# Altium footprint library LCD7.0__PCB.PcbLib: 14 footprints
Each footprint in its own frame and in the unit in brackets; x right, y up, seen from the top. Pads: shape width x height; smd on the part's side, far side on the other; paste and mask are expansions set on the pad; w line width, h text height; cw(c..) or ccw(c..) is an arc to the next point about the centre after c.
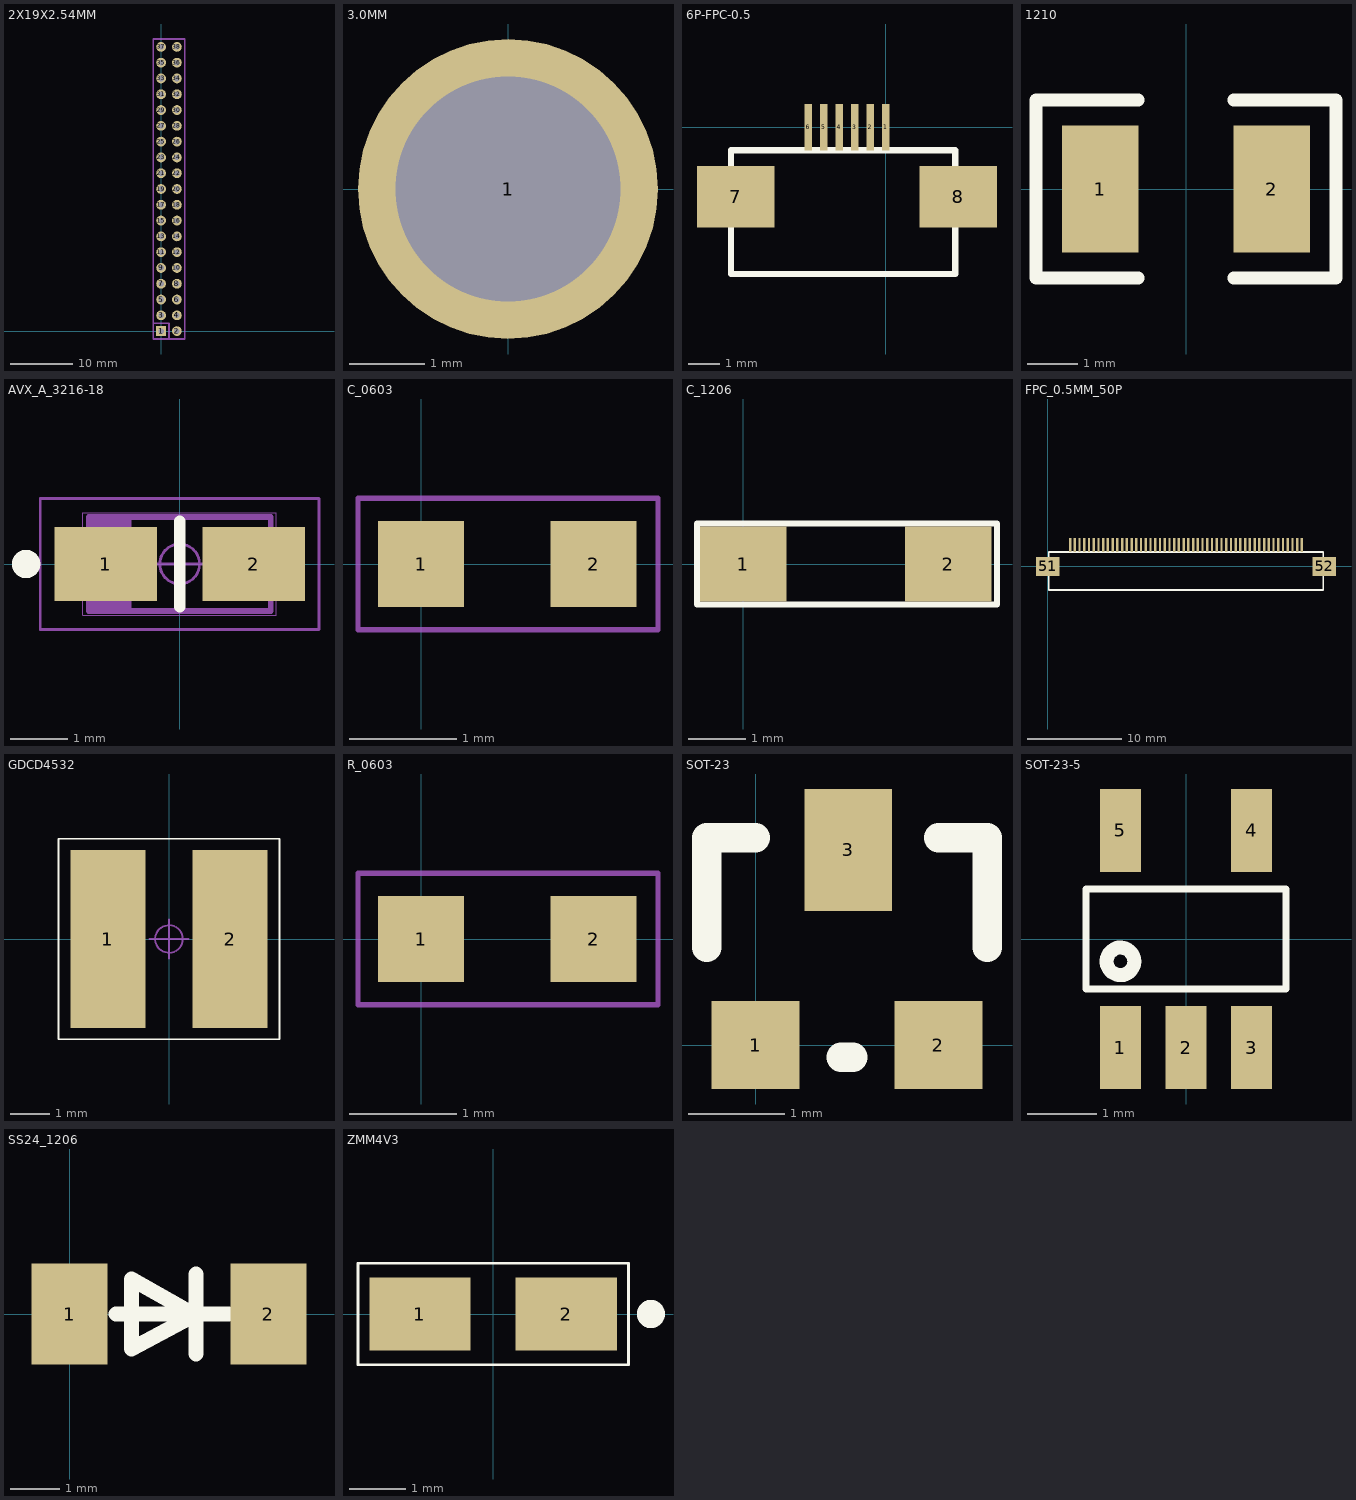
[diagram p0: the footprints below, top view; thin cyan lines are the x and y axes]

## 2X19X2.54MM [mil]
pads (38):
  rrect0% 62x62 hole 35.43: 1(0,0)
  round 62 hole 35.43: 2(100,0) 3(0,100) 4(100,100) 5(0,200) 6(100,200) 7(0,300) 8(100,300) 9(0,400) 10(100,400) 11(0,500) 12(100,500) 13(0,600) 14(100,600) 15(0,700) 16(100,700) 17(0,800) 18(100,800) 19(0,900) 20(100,900) 21(0,1000) 22(100,1000) 23(0,1100) 24(100,1100) 25(0,1200) 26(100,1200) 27(0,1300) 28(100,1300) 29(0,1400) 30(100,1400) 31(0,1500) 32(100,1500) 33(0,1600) 34(100,1600) 35(0,1700) 36(100,1700) 37(0,1800) 38(100,1800)
Mechanical 1:
  lines w12: -50,50 50,50 50,-50 ; -50,-50 150,-50 150,1850 -50,1850 -50,-50

## 3.0MM [mm]
pads (1):
  round 4 hole 3: 1(0,0)

## 6P-FPC-0.5 [mm]
height 5.3
pads (8):
  rect 0.25x1.5 smd: 1(0,0) 2(-0.5,0) 3(-1,0) 4(-1.5,0) 5(-2,0) 6(-2.5,0)
  rect 2.5x2 smd: 7(-4.85,-2.25) 8(2.35,-2.25)
Top Overlay:
  lines w0.2: -5,-4.75 2.25,-4.75 2.25,-0.75 -5,-0.75 -5,-4.75

## 1210 [mil]
pads (2):
  rect 60x100 smd: 1(-67.5,0) 2(67.5,0)
Top Overlay:
  lines w10: -37.5,-70 -118,-70 -118,70 -37.5,70 ; 37.5,-70 118,-70 118,70 37.5,70

## AVX_A_3216-18 [mm]
height 1.6
pads (2):
  rect 1.8x1.3 smd: 1(-1.3,0) 2(1.3,0)
Top Overlay:
  circle w0.25: c-2.7,0 r0.125
  lines w0.2: 0,-0.75 0,0.75
Mechanical 1:
  lines w0.1: -1.5,-0.825 -1.5,0.825 ; -1.4,-0.825 -1.4,0.825 ; -1.3,-0.825 -1.3,0.825 ; -1.2,-0.825 -1.2,0.825 ; -1.1,-0.825 -1.1,0.825 ; -1,-0.825 -1,0.825 ; -0.9,-0.825 -0.9,0.825 ; -1.6,-0.825 1.6,-0.825 1.6,0.825 -1.6,0.825 -1.6,-0.825
Mechanical 16:
  circle w0.05: c0,0 r0.35
  lines w0.001: -1.7,-0.9 1.7,-0.9 1.7,0.9 -1.7,0.9 -1.7,-0.9
  lines w0.05: -0.5,0 0.5,0 ; 0,-0.5 0,0.5 ; -2.45,-1.15 2.45,-1.15 2.45,1.15 -2.45,1.15 -2.45,-1.15

## C_0603 [mm]
pads (2):
  rect 0.8x0.8 smd: 1(0,0) 2(1.6,0)
Mechanical 1:
  lines w0.051: -0.584,-0.61 2.197,-0.61 2.197,0.61 -0.584,0.61 -0.584,-0.61

## C_1206 [mm]
pads (2):
  rect 1.5x1.3 smd: 1(0,0) 2(3.556,0)
Top Overlay:
  lines w0.1: -0.8,-0.7 -0.8,0.7 4.4,0.7 4.4,-0.7 -0.8,-0.7

## FPC_0.5MM_50P [mm]
pads (52):
  rect 0.25x1.5 smd: 1(26.85,2.25) 2(26.35,2.25) 3(25.85,2.25) 4(25.35,2.25) 5(24.85,2.25) 6(24.35,2.25) 7(23.85,2.25) 8(23.35,2.25) 9(22.85,2.25) 10(22.35,2.25) 11(21.85,2.25) 12(21.35,2.25) 13(20.85,2.25) 14(20.35,2.25) 15(19.85,2.25) 16(19.35,2.25) 17(18.85,2.25) 18(18.35,2.25) 19(17.85,2.25) 20(17.35,2.25) 21(16.85,2.25) 22(16.35,2.25) 23(15.85,2.25) 24(15.35,2.25) 25(14.85,2.25) 26(14.35,2.25) 27(13.85,2.25) 28(13.35,2.25) 29(12.85,2.25) 30(12.35,2.25) 31(11.85,2.25) 32(11.35,2.25) 33(10.85,2.25) 34(10.35,2.25) 35(9.85,2.25) 36(9.35,2.25) 37(8.85,2.25) 38(8.35,2.25) 39(7.85,2.25) 40(7.35,2.25) 41(6.85,2.25) 42(6.35,2.25) 43(5.85,2.25) 44(5.35,2.25) 45(4.85,2.25) 46(4.35,2.25) 47(3.85,2.25) 48(3.35,2.25) 49(2.85,2.25) 50(2.35,2.25)
  rect 2.5x2 smd: 51(0,0) 52(29.2,0)
Top Overlay:
  lines w0.2: 0.1,-2.5 29.1,-2.5 29.1,1.5 0.1,1.5 0.1,-2.5

## GDCD4532 [mm]
height 5.3
pads (2):
  rect 1.9x4.5 smd: 1(-1.55,0) 2(1.55,0)
Top Overlay:
  lines w0.05: -2.794,-2.54 2.794,-2.54 2.794,2.54 -2.794,2.54 -2.794,-2.54
Mechanical 16:
  circle w0.05: c0,0 r0.35
  lines w0.05: -0.5,0 0.5,0 ; 0,-0.5 0,0.5

## R_0603 [mm]
pads (2):
  rect 0.8x0.8 smd: 1(0,0) 2(1.6,0)
Mechanical 1:
  lines w0.051: -0.584,-0.61 2.197,-0.61 2.197,0.61 -0.584,0.61 -0.584,-0.61

## SOT-23 [mil]
pads (3):
  rect 36x36 smd: 1(0,0) 2(75,0)
  rect 36x50 smd: 3(38,80)
Top Overlay:
  lines w12: -20,40 -20,85 0,85 ; 35,-5 40,-5 ; 75,85 95,85 95,40

## SOT-23-5 [mm]
pads (5):
  rect 0.6x1.2 smd: 1(-0.95,-1.575) 2(0,-1.575) 3(0.95,-1.575) 4(0.95,1.575) 5(-0.95,1.575)
Top Overlay:
  circle w0.203: c-0.95,-0.325 r0.2
  lines w0.102: -1.45,-0.725 1.45,-0.725 1.45,0.475 1.45,0.725 -1.45,0.725 -1.45,0.475 -1.45,-0.725

## SS24_1206 [mil]
pads (2):
  rect 60x80 smd: 1(0,0) 2(157.48,0)
Top Overlay:
  lines w12: 36.92,-0.13 125.98,-0.13 ; 100.17,-31.5 100.17,31.5 ; 49.17,-27.56 100.17,-0.13 100.17,-1.13 49.17,27.56 49.17,-27.56

## ZMM4V3 [mm]
height 1.6
pads (2):
  rect 1.8x1.3 smd: 1(-1.3,0) 2(1.3,0)
Top Overlay:
  circle w0.25: c2.8,0 r0.125
  lines w0.05: -2.4,-0.9 2.4,-0.9 2.4,0.9 -2.4,0.9 -2.4,-0.9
